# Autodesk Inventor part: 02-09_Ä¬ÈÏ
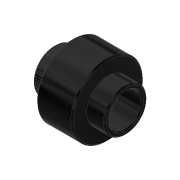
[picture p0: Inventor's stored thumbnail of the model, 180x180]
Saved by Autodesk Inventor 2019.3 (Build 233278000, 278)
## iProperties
Created: 2010-06
Part Number: 02-09_Ä¬ÈÏ
Material: Ogólny
Document SubType Name: Modeling
Designer: CADENGINEERING4
Density: 1 g/cm^3
Appearance: Gładki — czarny
Author: CADENGINEERING4
Revision Number: ÈÎºÎ
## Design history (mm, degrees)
feature "NONE"
node "Bryła1"
